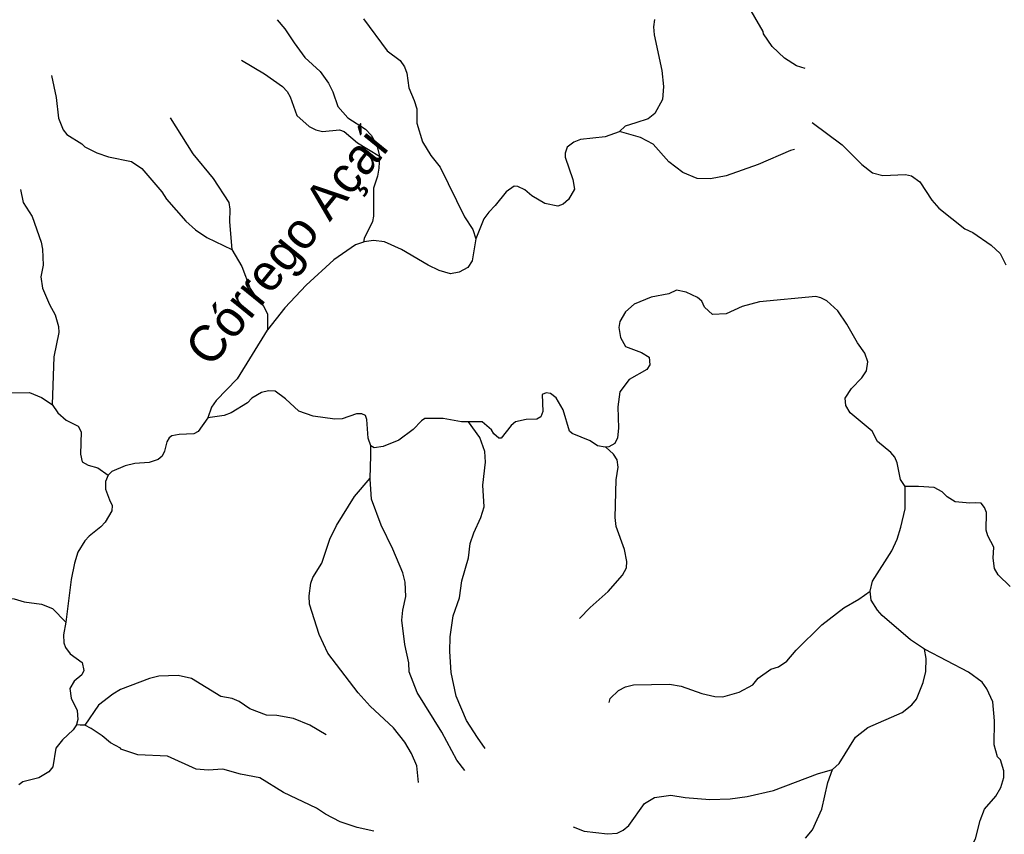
# Model space of a CAD drawing. Extents: x 500 to 555.2, y 9115.7 to 9171.
# Drawn here: x 504.79 to 510.22, y 9143.26 to 9147.75 of the extents above; entities that cross this region are included whole.
import ezdxf
from ezdxf.enums import TextEntityAlignment as Align

# ---------------------------------------------------------------- set-up
doc = ezdxf.new("R2010")
doc.units = 0
doc.header["$LTSCALE"] = 0.064
doc.layers.add('61', color=7, linetype='Continuous')
doc.layers.add('7', color=7, linetype='Continuous', lineweight=25)

msp = doc.modelspace()

# ---------------------------------------------------------------- linework, layer by layer
at = {"layer": '7'}
for points in [[(509.1198, 9147.4831), (509.0721, 9147.4973), (509.0061, 9147.5407), (508.937, 9147.6044), (508.8889, 9147.6738), (508.8877, 9147.6868), (508.7966, 9147.8449), (508.7457, 9147.8957), (508.6873, 9147.9273), (508.6439, 9147.9415), (508.5792, 9147.94), (508.5079, 9147.9227)], [(506.2083, 9147.751), (506.2508, 9147.7021), (506.3008, 9147.6242), (506.3612, 9147.5442), (506.4451, 9147.4669), (506.4916, 9147.4025), (506.5142, 9147.3548), (506.5427, 9147.2729), (506.5976, 9147.2113), (506.6942, 9147.149), (506.7252, 9147.1161), (506.7579, 9147.0602), (506.7728, 9146.9999)], [(506.6841, 9147.7562), (506.8142, 9147.5803), (506.8863, 9147.5275), (506.9102, 9147.4922), (506.9236, 9147.4567), (506.934, 9147.3764), (506.9641, 9147.3073), (506.9773, 9147.2616), (506.9777, 9147.1823), (507.0098, 9147.0786), (507.0547, 9147.004), (507.1064, 9146.939), (507.2406, 9146.6659), (507.286, 9146.5958), (507.3038, 9146.5429)], [(508.289, 9147.7538), (508.2823, 9147.7139), (508.2864, 9147.6684), (508.329, 9147.4716), (508.339, 9147.3839), (508.3321, 9147.3128), (508.2896, 9147.2348), (508.2536, 9147.2053), (508.1855, 9147.1831), (508.1277, 9147.1657), (508.0954, 9147.1353)], [(506.0113, 9147.5285), (506.1382, 9147.454), (506.2368, 9147.3832), (506.2636, 9147.3564), (506.2801, 9147.327), (506.3169, 9147.2232), (506.3833, 9147.1629), (506.4204, 9147.1452), (506.4582, 9147.1364), (506.5516, 9147.1455), (506.5778, 9147.136), (506.6503, 9147.0734), (506.7728, 9146.9999)], [(504.9631, 9147.4442), (504.9895, 9147.3227), (505.0014, 9147.2098), (505.0276, 9147.1456), (505.0477, 9147.119), (505.1301, 9147.0673), (505.1478, 9147.0505), (505.2132, 9147.0179), (505.277, 9146.9957), (505.405, 9146.9708), (505.4618, 9146.9312), (505.5725, 9146.8028), (505.5981, 9146.7624), (505.7035, 9146.6405), (505.7566, 9146.5938), (505.819, 9146.551), (505.9576, 9146.4851)], [(505.6181, 9147.2112), (505.7424, 9147.0117), (505.8555, 9146.877), (505.9405, 9146.7432), (505.9474, 9146.7066), (505.9442, 9146.6371), (505.9576, 9146.4851)], [(509.1587, 9147.1846), (509.3231, 9147.0624), (509.4324, 9146.9531), (509.4915, 9146.907), (509.5483, 9146.8935), (509.6718, 9146.8985), (509.7064, 9146.8919), (509.751, 9146.8575), (509.818, 9146.7564), (509.8567, 9146.7127), (510.0007, 9146.5983), (510.0443, 9146.5785), (510.146, 9146.5085), (510.1938, 9146.462), (510.2253, 9146.3998)], [(508.0954, 9147.1353), (508.0944, 9147.1344), (508.0159, 9147.1065), (507.8804, 9147.092), (507.8431, 9147.0768), (507.807, 9147.0485), (507.7965, 9147.0166), (507.7962, 9146.9936), (507.8386, 9146.8705), (507.8466, 9146.8171), (507.8149, 9146.7613), (507.7845, 9146.7345), (507.755, 9146.7247), (507.6835, 9146.7391), (507.6129, 9146.7816), (507.5739, 9146.8134), (507.5346, 9146.8328), (507.5144, 9146.8338), (507.4705, 9146.8033), (507.41, 9146.7273), (507.3745, 9146.6917), (507.348, 9146.6533), (507.3038, 9146.5429)], [(509.0606, 9147.036), (509.0389, 9147.0314), (508.861, 9146.9532), (508.6841, 9146.8916), (508.5981, 9146.8739), (508.5235, 9146.8771), (508.4445, 9146.9096), (508.3669, 9146.969), (508.2818, 9147.0665), (508.211, 9147.1034), (508.0954, 9147.1353)], [(506.7728, 9146.9999), (506.7678, 9146.9327), (506.7609, 9146.8902), (506.7398, 9146.824), (506.7395, 9146.669), (506.7341, 9146.6396), (506.6879, 9146.5453), (506.6833, 9146.5254)], [(504.7923, 9146.8166), (504.8074, 9146.7448), (504.8568, 9146.6665), (504.9058, 9146.5261), (504.914, 9146.4861), (504.9172, 9146.3982), (504.9043, 9146.3337), (504.9138, 9146.2716), (504.9515, 9146.1822), (504.9827, 9146.1248), (505.0026, 9146.0596), (505.0042, 9146.027), (504.9764, 9145.8923), (504.9661, 9145.6302)], [(506.6833, 9146.5254), (506.6393, 9146.5098), (506.5204, 9146.4283), (506.3668, 9146.2875), (506.2497, 9146.164), (506.154, 9146.0409)], [(507.3038, 9146.5429), (507.2823, 9146.4225), (507.259, 9146.3862), (507.211, 9146.36), (507.1635, 9146.3507), (507.1016, 9146.3688), (507.0405, 9146.3978), (506.8938, 9146.4851), (506.799, 9146.5263), (506.7387, 9146.5341), (506.6872, 9146.5268), (506.6833, 9146.5254)], [(505.9576, 9146.4851), (506.0133, 9146.391), (506.0583, 9146.2701), (506.0888, 9146.2251), (506.1339, 9146.1699), (506.1543, 9146.1278), (506.154, 9146.0409)], [(509.6709, 9145.1785), (509.6453, 9145.2167), (509.6265, 9145.309), (509.6146, 9145.339), (509.5921, 9145.3647), (509.5188, 9145.4252), (509.4882, 9145.4832), (509.3678, 9145.5844), (509.3428, 9145.6246), (509.3403, 9145.6644), (509.3757, 9145.719), (509.431, 9145.7774), (509.4577, 9145.8165), (509.4658, 9145.8655), (509.4493, 9145.9126), (509.4075, 9145.9698), (509.3493, 9146.0733), (509.2997, 9146.146), (509.2389, 9146.2015), (509.2056, 9146.219), (509.1781, 9146.2254), (508.8672, 9146.1963), (508.7721, 9146.1701), (508.684, 9146.1294), (508.6085, 9146.1267), (508.5641, 9146.1666), (508.5487, 9146.1996), (508.5259, 9146.2193), (508.4636, 9146.2504), (508.4107, 9146.2599), (508.3679, 9146.2405), (508.2694, 9146.2224), (508.177, 9146.1839), (508.1294, 9146.1411), (508.0968, 9146.0872), (508.0914, 9146.0554), (508.1016, 9145.9991), (508.1291, 9145.9507), (508.217, 9145.9177), (508.2592, 9145.8918), (508.2634, 9145.8483), (508.2467, 9145.8227), (508.1483, 9145.7677), (508.0969, 9145.7004)], [(506.154, 9146.0409), (506.1527, 9146.0392), (505.9863, 9145.771), (505.872, 9145.6518), (505.8463, 9145.6157), (505.8258, 9145.5558)], [(504.025, 9145.755), (504.1332, 9145.6764), (504.1907, 9145.6206), (504.2553, 9145.5029), (504.3089, 9145.4832), (504.3412, 9145.4902), (504.3838, 9145.53), (504.4076, 9145.5603), (504.4528, 9145.5972), (504.569, 9145.6352), (504.658, 9145.6866), (504.6948, 9145.6948), (504.8418, 9145.6959), (504.9075, 9145.6682), (504.9661, 9145.6302)], [(506.725, 9145.402), (506.7242, 9145.4025), (506.7088, 9145.4436), (506.702, 9145.5468), (506.6957, 9145.5687), (506.674, 9145.5794), (506.6444, 9145.578), (506.5657, 9145.5506), (506.5264, 9145.5485), (506.4061, 9145.5651), (506.328, 9145.5929), (506.2536, 9145.6621), (506.1966, 9145.7041), (506.1606, 9145.7058), (506.1207, 9145.6956), (506.0672, 9145.6648), (506.0446, 9145.6397), (505.9534, 9145.5843), (505.9146, 9145.5699), (505.8258, 9145.5558)], [(508.0197, 9145.3943), (508.0168, 9145.3939), (507.9749, 9145.4027), (507.9332, 9145.429), (507.8342, 9145.4706), (507.82, 9145.4836), (507.7845, 9145.6009), (507.747, 9145.666), (507.7144, 9145.6908), (507.6908, 9145.6942), (507.6695, 9145.6844), (507.6729, 9145.5907), (507.6625, 9145.5615), (507.6401, 9145.5487), (507.5811, 9145.5468), (507.5222, 9145.5336), (507.4976, 9145.5139), (507.4438, 9145.445), (507.4304, 9145.4437), (507.4029, 9145.4677), (507.3899, 9145.4902), (507.3381, 9145.5335), (507.2622, 9145.5346)], [(508.0969, 9145.7004), (508.0864, 9145.618), (508.0897, 9145.4997), (508.0847, 9145.4458), (508.0696, 9145.4157), (508.0366, 9145.3966), (508.0197, 9145.3943)], [(504.9661, 9145.6302), (504.9976, 9145.5832), (505.044, 9145.5437), (505.1108, 9145.5106), (505.1272, 9145.4799), (505.124, 9145.3556), (505.1328, 9145.3135), (505.1653, 9145.2948), (505.2185, 9145.2813), (505.2756, 9145.2396)], [(505.8258, 9145.5558), (505.7715, 9145.4809), (505.7479, 9145.4684), (505.6672, 9145.4647), (505.6276, 9145.4565), (505.6113, 9145.4464), (505.6, 9145.4243), (505.5869, 9145.3727), (505.5736, 9145.3458), (505.5507, 9145.3274), (505.5018, 9145.3109), (505.4225, 9145.304), (505.3701, 9145.2925), (505.2967, 9145.2613), (505.2756, 9145.2396)], [(507.2622, 9145.5346), (507.2248, 9145.5351), (507.1237, 9145.5535), (507.0229, 9145.5534), (507.0036, 9145.5404), (506.9568, 9145.4924), (506.878, 9145.434), (506.793, 9145.3983), (506.7421, 9145.3905), (506.725, 9145.402)], [(507.3546, 9143.7328), (507.3125, 9143.7936), (507.2524, 9143.8865), (507.1945, 9144.0218), (507.1676, 9144.1522), (507.1597, 9144.2684), (507.1614, 9144.3491), (507.1792, 9144.4646), (507.2137, 9144.5643), (507.2266, 9144.6581), (507.2627, 9144.7836), (507.2728, 9144.8628), (507.2927, 9144.9225), (507.3316, 9145.0067), (507.3497, 9145.0656), (507.3417, 9145.1844), (507.3563, 9145.3116), (507.3531, 9145.3713), (507.3249, 9145.4473), (507.2622, 9145.5346)], [(506.72, 9145.2235), (506.725, 9145.3477), (506.725, 9145.402)], [(507.8751, 9144.45), (507.9339, 9144.5101), (508.0334, 9144.5983), (508.1125, 9144.689), (508.1339, 9144.7289), (508.1355, 9144.7644), (508.1224, 9144.83), (508.0769, 9144.9578), (508.0718, 9145.0073), (508.0766, 9145.2148), (508.088, 9145.2839), (508.0822, 9145.3246), (508.062, 9145.3559), (508.0197, 9145.3943)], [(505.2756, 9145.2396), (505.2603, 9145.2061), (505.2618, 9145.1626), (505.2827, 9145.1038), (505.2976, 9145.0728), (505.2962, 9145.0439), (505.2601, 9144.981), (505.236, 9144.9552), (505.1705, 9144.9043), (505.1477, 9144.8779), (505.1083, 9144.815), (505.0896, 9144.7545), (505.0712, 9144.6645), (505.0419, 9144.4301)], [(506.9863, 9143.545), (506.9773, 9143.6365), (506.9476, 9143.7054), (506.9119, 9143.7671), (506.8495, 9143.8458), (506.72, 9143.9656), (506.654, 9144.0392), (506.4879, 9144.2588), (506.4391, 9144.361), (506.3853, 9144.5289), (506.3839, 9144.5755), (506.3943, 9144.6452), (506.4049, 9144.6753), (506.4541, 9144.7545), (506.4988, 9144.8864), (506.5357, 9144.9633), (506.6351, 9145.1224), (506.72, 9145.2235)], [(507.2425, 9143.6116), (507.1988, 9143.6682), (507.1155, 9143.8224), (506.9798, 9144.0416), (506.9355, 9144.1554), (506.9333, 9144.2055), (506.9113, 9144.3071), (506.8955, 9144.4396), (506.9011, 9144.496), (506.9168, 9144.5708), (506.9133, 9144.651), (506.9004, 9144.7021), (506.8449, 9144.8327), (506.7809, 9144.9639), (506.7285, 9145.1073), (506.7197, 9145.2173), (506.72, 9145.2235)], [(509.4775, 9144.6003), (509.4905, 9144.6554), (509.597, 9144.8235), (509.6259, 9144.8877), (509.6476, 9144.9541), (509.6708, 9145.0538), (509.6709, 9145.1785)], [(510.25, 9144.627), (510.1832, 9144.6902), (510.1629, 9144.7257), (510.1564, 9144.7827), (510.1596, 9144.8424), (510.1272, 9144.905), (510.1173, 9144.9377), (510.1187, 9145.034), (510.108, 9145.0617), (510.0897, 9145.085), (510.0579, 9145.0879), (510.0269, 9145.0859), (509.9459, 9145.0928), (509.9027, 9145.12), (509.8746, 9145.1491), (509.8305, 9145.1726), (509.7444, 9145.1786), (509.6709, 9145.1785)], [(503.7022, 9144.8967), (503.7849, 9144.8972), (503.8577, 9144.871), (503.9561, 9144.812), (504.1081, 9144.6991), (504.2008, 9144.6572), (504.3401, 9144.619), (504.457, 9144.5544), (504.5433, 9144.5479), (504.6465, 9144.5643), (504.7566, 9144.5576), (504.8121, 9144.5407), (504.9075, 9144.5281), (504.9691, 9144.5042), (505.0419, 9144.4301)], [(508.0385, 9143.9856), (508.0434, 9144.009), (508.0897, 9144.0524), (508.1285, 9144.0719), (508.1723, 9144.0836), (508.3707, 9144.0883), (508.4364, 9144.0765), (508.5495, 9144.036), (508.6214, 9144.0194), (508.6651, 9144.0184), (508.7556, 9144.0427), (508.831, 9144.0838), (508.8606, 9144.1214), (508.9295, 9144.1705), (508.9718, 9144.1837), (509.0175, 9144.2146), (509.0706, 9144.2756), (509.2116, 9144.415), (509.3335, 9144.5089), (509.4145, 9144.5558), (509.4775, 9144.6003)], [(509.7772, 9144.2808), (509.7005, 9144.3314), (509.5442, 9144.4663), (509.518, 9144.4959), (509.4839, 9144.5503), (509.4775, 9144.6003)], [(505.0419, 9144.4301), (505.0302, 9144.3604), (505.0322, 9144.3158), (505.0413, 9144.2902), (505.0666, 9144.2544), (505.1315, 9144.2071), (505.1417, 9144.1627), (505.131, 9144.1388), (505.0884, 9144.1037), (505.0636, 9144.0638), (505.0716, 9144.01), (505.1043, 9143.9418), (505.1078, 9143.8919), (505.102, 9143.8658), (505.1008, 9143.8639), (505.0832, 9143.8349)], [(509.2708, 9143.6177), (509.3062, 9143.6504), (509.3967, 9143.7951), (509.4648, 9143.8494), (509.6541, 9143.932), (509.7075, 9143.9744), (509.7331, 9144.0053), (509.7704, 9144.097), (509.7857, 9144.1582), (509.7873, 9144.2291), (509.7772, 9144.2808)], [(509.5976, 9142.764), (509.6083, 9142.8369), (509.6611, 9142.9009), (509.8207, 9142.9818), (509.9108, 9143.0458), (509.9839, 9143.1154), (510.0205, 9143.1592), (510.059, 9143.2342), (510.0847, 9143.3356), (510.1092, 9143.3988), (510.1699, 9143.4692), (510.1991, 9143.5169), (510.2152, 9143.5729), (510.2154, 9143.609), (510.1973, 9143.6702), (510.1807, 9143.6874), (510.1615, 9143.7534), (510.1629, 9143.8859), (510.1547, 9143.9895), (510.1218, 9144.0624), (510.0951, 9144.0988), (510.0202, 9144.1542), (509.7809, 9144.2784), (509.7772, 9144.2808)], [(506.4787, 9143.8085), (506.3886, 9143.8615), (506.2984, 9143.8983), (506.2055, 9143.9149), (506.1497, 9143.9166), (506.0572, 9143.9519), (505.9982, 9143.9917), (505.9595, 9144.0079), (505.8979, 9144.0196), (505.7357, 9144.118), (505.662, 9144.1344), (505.5556, 9144.1309), (505.5039, 9144.1179), (505.3435, 9144.0588), (505.3011, 9144.0328), (505.2229, 9143.9725), (505.1463, 9143.8613)], [(505.1463, 9143.8613), (505.1206, 9143.8619), (505.1008, 9143.8639)], [(506.7403, 9143.2761), (506.6488, 9143.2965), (506.555, 9143.329), (506.474, 9143.3702), (506.4242, 9143.4032), (506.2423, 9143.4903), (506.1125, 9143.5703), (506.0053, 9143.592), (505.9086, 9143.6193), (505.8273, 9143.613), (505.7604, 9143.6179), (505.6029, 9143.6899), (505.4385, 9143.6985), (505.3463, 9143.7291), (505.3444, 9143.7347), (505.288, 9143.7634), (505.242, 9143.8031), (505.1819, 9143.843), (505.1463, 9143.8613)], [(505.0832, 9143.8349), (505.0235, 9143.7798), (504.9881, 9143.7338), (504.9701, 9143.6308), (504.9494, 9143.604), (504.8943, 9143.5703), (504.8049, 9143.5493), (504.7835, 9143.5318)], [(507.8402, 9143.3005), (507.9014, 9143.2771), (508.0301, 9143.2619), (508.0825, 9143.2651), (508.1164, 9143.2819), (508.1478, 9143.3086), (508.2331, 9143.43), (508.2887, 9143.4622), (508.3783, 9143.4751), (508.457, 9143.4621), (508.5936, 9143.4506), (508.7058, 9143.4554), (508.7991, 9143.4676), (508.944, 9143.5018), (509.188, 9143.593), (509.2708, 9143.6177)], [(509.1221, 9143.2382), (509.1607, 9143.2833), (509.2115, 9143.3981), (509.2439, 9143.5451), (509.2708, 9143.6177)]]:
    msp.add_lwpolyline(points, dxfattribs=at)

# ---------------------------------------------------------------- texts
at = {"layer": '61'}
msp.add_text('Córrego Açaí', height=0.2, rotation=50.906, dxfattribs=at).set_placement((506.3382, 9146.4381), align=Align.CENTER)

doc.saveas('drawing.dxf')
